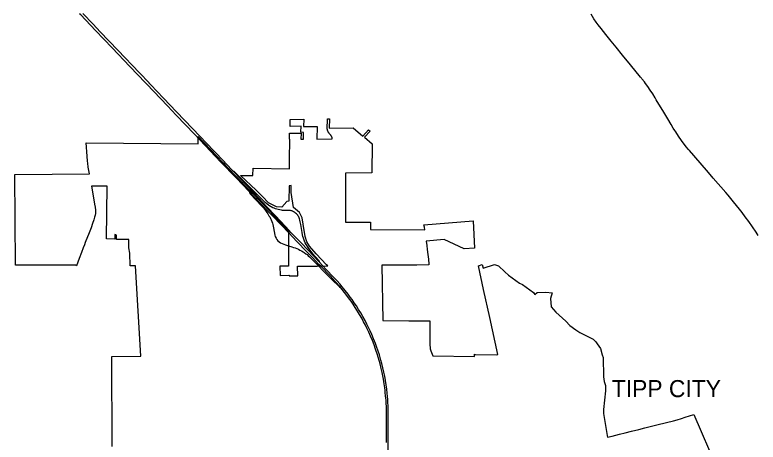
# Model space of a CAD drawing. Extents: x 0 to 34, y 0 to 22.
# Drawn here: x 5.1578 to 5.5075, y 16.3838 to 16.5849 of the extents above; entities that cross this region are included whole.
import ezdxf

# ---------------------------------------------------------------- set-up
doc = ezdxf.new("R2010")
doc.units = 0
for name, color, linetype in [('GM_X_Corporation', 7, 'Continuous'), ('GM_X_Corporation_Text', 7, 'Continuous'), ('GM_X_Interchange_Ramps', 7, 'Continuous'), ('GM_X_Interstate_Route', 7, 'Continuous'), ('GM_X_State_Route', 7, 'Continuous')]:
    doc.layers.add(name, color=color, linetype=linetype)

msp = doc.modelspace()

# ---------------------------------------------------------------- linework, layer by layer
at = {"layer": 'GM_X_Corporation'}
msp.add_lwpolyline([(5.20354, 16.38183), (5.20336, 16.42421), (5.21713, 16.42432), (5.2146, 16.46688), (5.212, 16.46686), (5.21196, 16.4727), (5.2115, 16.47524), (5.21148, 16.47817), (5.21149, 16.47917), (5.20907, 16.47918), (5.20568, 16.4792), (5.2057, 16.48118), (5.20536, 16.48145), (5.20489, 16.48155), (5.20488, 16.47943), (5.20086, 16.47948), (5.20118, 16.50432), (5.19385, 16.5043), (5.19546, 16.49506), (5.19552, 16.49471), (5.19564, 16.49388), (5.19567, 16.49364), (5.19569, 16.49342), (5.19574, 16.49297), (5.19576, 16.49271), (5.19577, 16.49248), (5.19578, 16.4922), (5.19576, 16.49187), (5.19573, 16.49137), (5.1956, 16.49068), (5.19535, 16.48971), (5.19494, 16.48839), (5.19439, 16.48673), (5.19363, 16.48465), (5.19274, 16.48234), (5.19093, 16.47772), (5.19055, 16.47674), (5.18998, 16.47526), (5.18912, 16.47305), (5.18809, 16.47033), (5.1868, 16.46688), (5.18628, 16.46709), (5.15812, 16.46712), (5.15781, 16.50978), (5.19286, 16.51006), (5.19236, 16.51328), (5.1921, 16.51516), (5.192, 16.51605), (5.19179, 16.51836), (5.19134, 16.52468), (5.244, 16.52415), (5.24402, 16.52773), (5.2615, 16.50939), (5.27511, 16.49528), (5.28661, 16.48311), (5.2866, 16.48198), (5.28654, 16.47358), (5.28654, 16.47323), (5.28652, 16.46661), (5.28247, 16.46659), (5.28263, 16.46221), (5.28671, 16.46245), (5.2868, 16.46244), (5.28681, 16.46217), (5.29088, 16.46208), (5.29071, 16.46664), (5.29803, 16.46667), (5.29998, 16.46668), (5.30434, 16.46674), (5.30501, 16.46675), (5.30448, 16.46731), (5.29961, 16.47242), (5.2964, 16.47602), (5.29509, 16.4781), (5.2943, 16.48068), (5.29344, 16.48637), (5.29297, 16.48946), (5.29171, 16.49188), (5.28882, 16.49432), (5.28771, 16.50128), (5.28775, 16.50453), (5.2868, 16.50452), (5.2867, 16.49729), (5.28578, 16.4971), (5.28346, 16.49438), (5.28094, 16.49459), (5.27712, 16.4965), (5.27435, 16.49941), (5.27126, 16.50237), (5.26398, 16.50936), (5.26979, 16.50929), (5.26998, 16.51272), (5.28693, 16.51252), (5.28701, 16.51673), (5.28706, 16.52034), (5.28708, 16.52114), (5.28709, 16.52196), (5.28715, 16.52637), (5.28704, 16.52637), (5.28705, 16.52922), (5.29244, 16.52925), (5.2924, 16.52639), (5.29344, 16.5264), (5.29356, 16.5264), (5.29362, 16.52962), (5.29241, 16.52964), (5.29246, 16.53245), (5.28726, 16.53244), (5.28725, 16.53574), (5.29377, 16.5358), (5.29365, 16.53233), (5.29997, 16.53243), (5.29987, 16.52644), (5.3071, 16.52657), (5.3071, 16.52662), (5.30709, 16.52672), (5.30708, 16.52681), (5.30707, 16.52691), (5.30705, 16.527), (5.30703, 16.52709), (5.30701, 16.52719), (5.30698, 16.52728), (5.30695, 16.52737), (5.30692, 16.52746), (5.30689, 16.52755), (5.30685, 16.52764), (5.30681, 16.52772), (5.30676, 16.52781), (5.30671, 16.52789), (5.30666, 16.52797), (5.30661, 16.52805), (5.30656, 16.52813), (5.3065, 16.5282), (5.30644, 16.52828), (5.30641, 16.52831), (5.30571, 16.52909), (5.30569, 16.52912), (5.3056, 16.52922), (5.30552, 16.52932), (5.30545, 16.52942), (5.30538, 16.52953), (5.30531, 16.52964), (5.30524, 16.52975), (5.30518, 16.52986), (5.30515, 16.52992), (5.30512, 16.52998), (5.30507, 16.5301), (5.30502, 16.53022), (5.30498, 16.53034), (5.30494, 16.53046), (5.3049, 16.53059), (5.30487, 16.53071), (5.30485, 16.53084), (5.30482, 16.53096), (5.3048, 16.53109), (5.30485, 16.53595), (5.30582, 16.53597), (5.30574, 16.5316), (5.31693, 16.53179), (5.32147, 16.52783), (5.32421, 16.53088), (5.32496, 16.53021), (5.32231, 16.52732), (5.32584, 16.52423), (5.32573, 16.51052), (5.31331, 16.51041), (5.31328, 16.48734), (5.32509, 16.4873), (5.32515, 16.4839), (5.35067, 16.4838), (5.35045, 16.48501), (5.3502, 16.48617), (5.3734, 16.48795), (5.37397, 16.47513), (5.36914, 16.47474), (5.35976, 16.47922), (5.35132, 16.47841), (5.35155, 16.47635), (5.35179, 16.4745), (5.3521, 16.47218), (5.35225, 16.47101), (5.35237, 16.47), (5.35245, 16.46917), (5.3525, 16.46845), (5.35251, 16.46782), (5.35252, 16.4672), (5.34685, 16.46717), (5.34311, 16.46714), (5.33964, 16.46711), (5.33385, 16.46707), (5.33039, 16.46705), (5.33095, 16.4411), (5.3432, 16.44094), (5.35272, 16.44086), (5.35305, 16.44086), (5.35302, 16.42938), (5.35311, 16.42849), (5.35325, 16.42767), (5.35351, 16.42673), (5.35436, 16.42449), (5.37408, 16.42414), (5.37409, 16.42517), (5.3744, 16.42508), (5.38441, 16.42498), (5.38504, 16.42502), (5.38119, 16.44251), (5.37832, 16.45567), (5.37591, 16.46674), (5.37763, 16.46748), (5.37804, 16.46569), (5.38348, 16.46739), (5.38531, 16.46673), (5.38828, 16.46403), (5.38999, 16.46246), (5.39512, 16.45859), (5.39668, 16.45799), (5.40174, 16.45418), (5.40247, 16.45336), (5.40348, 16.45429), (5.40765, 16.45436), (5.41064, 16.45411), (5.40971, 16.45138), (5.41004, 16.4475), (5.41226, 16.44496), (5.41705, 16.44069), (5.41891, 16.4387), (5.42169, 16.43662), (5.4236, 16.43547), (5.42979, 16.43229), (5.43113, 16.43109), (5.43177, 16.43017), (5.43329, 16.42783), (5.43416, 16.42496), (5.4345, 16.42363), (5.43465, 16.41465), (5.43499, 16.41238), (5.43563, 16.41042), (5.43563, 16.40795), (5.43472, 16.39914), (5.43478, 16.39732), (5.43638, 16.38689), (5.43654, 16.38613), (5.43876, 16.38668), (5.44224, 16.38756), (5.44495, 16.38824), (5.44795, 16.389), (5.45129, 16.38985), (5.45421, 16.39059), (5.45984, 16.39198), (5.46429, 16.39311), (5.46762, 16.39393), (5.4694, 16.3944), (5.47133, 16.39495), (5.47319, 16.39552), (5.47522, 16.39617), (5.47723, 16.39682), (5.48805, 16.37175)], dxfattribs=at)
at = {"layer": 'GM_X_Interchange_Ramps'}
for points in [[(5.28665, 16.49288), (5.28544, 16.49289), (5.28443, 16.49289), (5.28406, 16.4929), (5.28374, 16.49291), (5.28324, 16.49296), (5.28243, 16.49308), (5.28171, 16.49325), (5.28111, 16.49342), (5.28036, 16.49367), (5.27981, 16.49388), (5.27919, 16.49416), (5.27843, 16.49453), (5.27802, 16.49476), (5.27726, 16.49524), (5.27638, 16.49591), (5.27563, 16.49657), (5.27385, 16.49827), (5.26575, 16.50644), (5.26348, 16.50869), (5.26331, 16.50887), (5.26123, 16.51092), (5.26111, 16.51102), (5.26095, 16.51113), (5.2608, 16.51119), (5.26061, 16.51123)], [(5.26817, 16.50155), (5.26819, 16.50141), (5.2682, 16.50132), (5.26824, 16.50118), (5.26836, 16.501), (5.26855, 16.50076), (5.27401, 16.49491), (5.27476, 16.4941), (5.27531, 16.49346), (5.27576, 16.49288), (5.27608, 16.4924), (5.27683, 16.49126), (5.27736, 16.49038), (5.27768, 16.48983), (5.27806, 16.48912), (5.27839, 16.48843), (5.27869, 16.48768), (5.27893, 16.48692), (5.27916, 16.48621), (5.27932, 16.4855), (5.27946, 16.48474), (5.2801, 16.48131), (5.28028, 16.48063), (5.28067, 16.47982), (5.28107, 16.47922), (5.28157, 16.47861), (5.28218, 16.47807), (5.28276, 16.47769), (5.28362, 16.4773), (5.28511, 16.47673), (5.28659, 16.47619)], [(5.3011, 16.46846), (5.30109, 16.46864), (5.30108, 16.4688), (5.30105, 16.46891), (5.301, 16.46902), (5.30089, 16.46917), (5.29907, 16.47123), (5.29805, 16.47242), (5.29714, 16.47359), (5.2966, 16.4743), (5.29582, 16.47537), (5.29525, 16.47619), (5.29483, 16.47686), (5.29438, 16.47769), (5.29405, 16.47841), (5.29385, 16.4789), (5.29356, 16.47975), (5.29333, 16.48062), (5.29314, 16.48144), (5.29294, 16.48253), (5.29232, 16.48628), (5.2921, 16.48752), (5.29193, 16.4883), (5.29175, 16.48891), (5.29157, 16.4894), (5.29136, 16.48988), (5.29115, 16.49025), (5.29088, 16.49064), (5.29065, 16.49092), (5.29024, 16.49134), (5.28987, 16.49164), (5.28953, 16.49189), (5.28931, 16.49202), (5.28889, 16.49223), (5.28838, 16.49247), (5.28803, 16.49261), (5.28774, 16.49271), (5.28744, 16.49278), (5.28713, 16.49283), (5.28665, 16.49288)], [(5.28659, 16.47619), (5.28817, 16.47572), (5.2889, 16.4755), (5.28967, 16.47523), (5.29045, 16.47492), (5.29116, 16.47459), (5.29189, 16.47424), (5.29259, 16.47389), (5.2934, 16.47337), (5.29397, 16.47301), (5.29463, 16.47253), (5.29524, 16.47208), (5.29586, 16.47154), (5.29645, 16.471), (5.30698, 16.46042), (5.31045, 16.45687), (5.3111, 16.45645)]]:
    msp.add_lwpolyline(points, dxfattribs=at)
at = {"layer": 'GM_X_Interstate_Route'}
for points in [[(5.26817, 16.50155), (5.26782, 16.50193), (5.26184, 16.50818), (5.25477, 16.51557), (5.24232, 16.52869), (5.23366, 16.53777), (5.22959, 16.54205), (5.21987, 16.55224), (5.21923, 16.55291), (5.21186, 16.56063), (5.20351, 16.56942), (5.19573, 16.5776), (5.18877, 16.58487), (5.18829, 16.58537)], [(5.221, 16.55281), (5.22094, 16.55287), (5.21642, 16.55757), (5.20628, 16.56826), (5.19796, 16.57694), (5.19462, 16.58046), (5.1898, 16.58548)], [(5.25696, 16.51507), (5.25637, 16.51569), (5.25146, 16.52085), (5.24143, 16.53139), (5.23392, 16.53924), (5.22777, 16.54569), (5.22182, 16.55196), (5.221, 16.55281)], [(5.3025, 16.46701), (5.3011, 16.46846), (5.3006, 16.46898), (5.29575, 16.47411), (5.29226, 16.47778), (5.2877, 16.48254), (5.28662, 16.48366), (5.2851, 16.48524), (5.28044, 16.49026), (5.27638, 16.49463), (5.27041, 16.50096), (5.26643, 16.5051), (5.264, 16.50767), (5.26061, 16.51123), (5.25696, 16.51507)], [(5.3111, 16.45645), (5.31076, 16.45688), (5.30848, 16.45944), (5.30609, 16.46205), (5.30169, 16.46669), (5.30086, 16.4675), (5.29775, 16.47078), (5.29745, 16.4711), (5.29518, 16.47338), (5.29047, 16.47828), (5.28662, 16.4824), (5.28624, 16.4828), (5.28359, 16.48564), (5.27846, 16.49087), (5.27273, 16.49678), (5.26817, 16.50155)], [(5.33344, 16.37845), (5.33345, 16.38756), (5.33347, 16.39605), (5.33345, 16.39853), (5.3334, 16.40058), (5.3333, 16.40274), (5.33325, 16.40359), (5.33309, 16.4057), (5.33302, 16.40652), (5.33298, 16.40695), (5.33277, 16.40873), (5.33247, 16.41087), (5.33215, 16.41284), (5.33178, 16.41486), (5.33139, 16.41682), (5.33093, 16.41888), (5.33046, 16.42077), (5.33004, 16.42234), (5.32933, 16.4249), (5.32858, 16.42716), (5.32815, 16.4284), (5.32745, 16.43028), (5.32659, 16.43243), (5.3257, 16.43457), (5.32495, 16.43625), (5.32424, 16.43777), (5.32346, 16.43933), (5.32256, 16.44105), (5.32155, 16.4429), (5.32052, 16.44468), (5.31954, 16.4463), (5.3185, 16.44794), (5.31748, 16.44947), (5.31649, 16.4509), (5.31562, 16.45209), (5.3146, 16.45343), (5.31318, 16.45526), (5.31178, 16.45697), (5.31062, 16.45833), (5.30936, 16.45975), (5.30771, 16.46152), (5.30429, 16.46511), (5.3025, 16.46701)], [(5.33262, 16.38367), (5.33258, 16.39906), (5.3324, 16.40362), (5.33223, 16.40555), (5.33205, 16.40728), (5.33193, 16.4083), (5.3318, 16.40933), (5.33152, 16.41126), (5.33116, 16.4135), (5.33086, 16.41511), (5.33057, 16.41656), (5.33013, 16.41852), (5.32959, 16.42072), (5.32917, 16.42231), (5.32842, 16.42492), (5.32752, 16.42757), (5.32677, 16.4296), (5.32599, 16.43162), (5.32512, 16.43372), (5.32431, 16.43555), (5.32355, 16.43718), (5.32269, 16.43894), (5.32187, 16.44053), (5.32096, 16.4422), (5.31999, 16.4439), (5.31906, 16.44543), (5.31797, 16.44718), (5.31696, 16.44873), (5.31597, 16.45017), (5.3148, 16.45179), (5.31356, 16.45344), (5.3111, 16.45645)]]:
    msp.add_lwpolyline(points, dxfattribs=at)
at = {"layer": 'GM_X_State_Route'}
for points in [[(5.49329, 16.5), (5.49221, 16.50128), (5.48637, 16.50807), (5.48405, 16.5108), (5.48014, 16.5153), (5.47513, 16.52105), (5.47472, 16.52152), (5.4736, 16.52286), (5.4733, 16.52323), (5.47264, 16.52406), (5.47141, 16.52578), (5.47002, 16.52777), (5.46868, 16.52979), (5.46825, 16.53046), (5.46753, 16.5316), (5.46649, 16.53333), (5.46496, 16.53591), (5.46304, 16.53919), (5.45956, 16.54498), (5.45904, 16.54584), (5.4579, 16.54767), (5.4567, 16.54947), (5.4555, 16.55121), (5.45449, 16.55258), (5.45392, 16.55334), (5.45276, 16.55483), (5.45252, 16.55513), (5.45211, 16.55564), (5.44741, 16.56142), (5.4437, 16.56596), (5.44061, 16.56976), (5.43838, 16.5725), (5.43574, 16.57574), (5.43354, 16.57848), (5.43214, 16.58026), (5.43123, 16.58153), (5.43023, 16.58304), (5.4289, 16.58519)], [(5.5075, 16.48106), (5.5065, 16.48261), (5.50303, 16.48765), (5.50142, 16.48994), (5.50001, 16.49185), (5.4987, 16.4935), (5.49581, 16.497), (5.49329, 16.5)]]:
    msp.add_lwpolyline(points, dxfattribs=at)

# ---------------------------------------------------------------- texts
at = {"layer": 'GM_X_Corporation_Text'}
msp.add_text('TIPP CITY', height=0.008037, rotation=0, dxfattribs=at).set_placement((5.43861, 16.40501))

doc.saveas('drawing.dxf')
